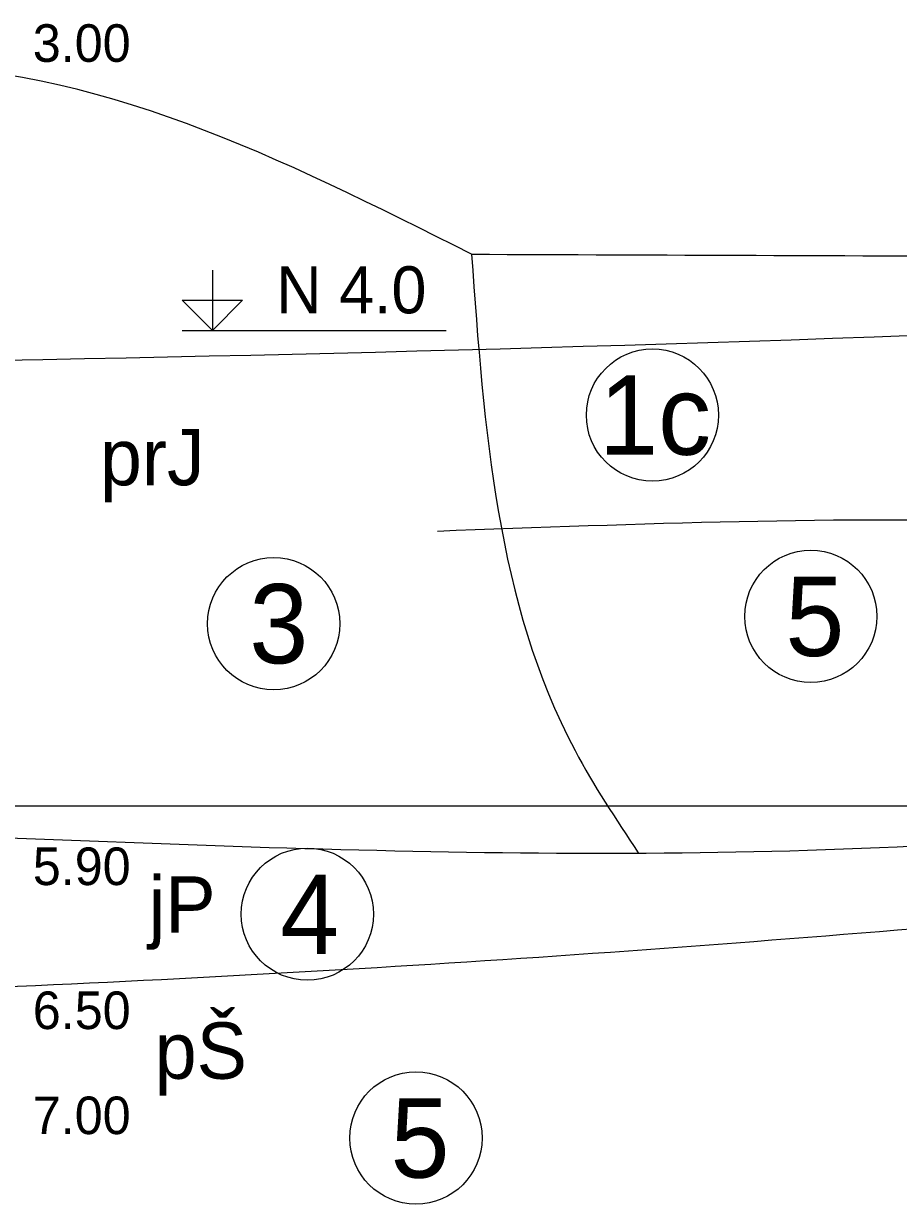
# Model space of a CAD drawing. Extents: x 3042 to 4120, y 576 to 2694.
# Drawn here: x 3433.83 to 3450.37, y 879.91 to 902.31 of the extents above; entities that cross this region are included whole.
import ezdxf

# ---------------------------------------------------------------- set-up
doc = ezdxf.new("R2010")
doc.units = 0
for name, color, linetype in [('52', 7, 'Continuous'), ('61', 7, 'Continuous'), ('HPV', 7, 'Continuous'), ('rozhraní', 7, 'Continuous')]:
    doc.layers.add(name, color=color, linetype=linetype)

msp = doc.modelspace()

# ---------------------------------------------------------------- linework, layer by layer
at = {"layer": '61'}
for points in [[(3437.3966062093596, 897.6520620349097), (3437.3966062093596, 896.5090620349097), (3436.8251062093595, 897.0805620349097), (3437.9681062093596, 897.0805620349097), (3437.3966062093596, 896.5090620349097)], [(3436.8251062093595, 896.5090620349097), (3441.8204562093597, 896.5090620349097)]]:
    msp.add_lwpolyline(points, dxfattribs=at)
at = {"layer": 'HPV'}
msp.add_spline([(3335.582962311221, 896.0481503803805), (3352.5717167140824, 896.0481503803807), (3453.0617167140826, 896.509755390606), (3557.3317167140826, 895.7898480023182), (3580.051716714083, 892.4898632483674), (3619.081666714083, 896.3928809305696), (3629.646992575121, 896.3928809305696)], degree=3, dxfattribs=at)
at = {"layer": 'rozhraní'}
for centre in [(3445.719485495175, 894.9085526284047), (3448.7150478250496, 891.1024646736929), (3438.5556742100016, 890.9639186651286), (3439.1920527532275, 885.4705530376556), (3441.2465060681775, 881.2381839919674)]:
    msp.add_circle(centre, 1.25, dxfattribs=at)
for points in [[(3442.2980689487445, 897.9504925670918), (3431.3317167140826, 901.5090620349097), (3430.030343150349, 901.4533469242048), (3426.6579803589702, 901.3354072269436), (3420.5505789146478, 901.1702916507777), (3409.5313912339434, 901.1164816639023), (3352.5717167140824, 896.4090620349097), (3327.8662573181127, 896.5362487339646)], [(3248.313660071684, 891.8591120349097), (3256.3217167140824, 891.8591120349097), (3352.5717167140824, 886.4090620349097), (3431.331691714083, 884.0090620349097), (3453.0617167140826, 885.4090620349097), (3491.5217167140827, 887.3591120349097), (3557.3317167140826, 884.6590620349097), (3580.051716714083, 895.0090120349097), (3619.0817167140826, 891.2590620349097), (3629.2745825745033, 891.2590620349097)], [(3442.2980689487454, 897.950492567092), (3453.0617167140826, 897.9090620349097), (3474.3006144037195, 897.8020620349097)], [(3442.2980689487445, 897.9504925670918), (3444.2548997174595, 888.5643431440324), (3445.451620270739, 886.6308541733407)], [(3441.6513317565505, 892.7166057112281), (3453.0631330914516, 892.8972495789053), (3455.728716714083, 892.801106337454)], [(3327.731251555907, 891.6486311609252), (3352.6357167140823, 891.4090620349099), (3372.3327436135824, 890.6912689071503), (3392.0153061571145, 889.3178217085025), (3411.682073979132, 887.8899946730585), (3431.3317167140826, 887.0090620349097), (3453.0617167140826, 886.9090620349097), (3491.5217167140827, 891.3591120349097), (3507.9473907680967, 889.8031245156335), (3524.476644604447, 888.6483564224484), (3540.9809344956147, 888.0489536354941), (3549.183548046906, 888.005684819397), (3553.26544223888, 888.0565884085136), (3557.3317167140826, 888.1590620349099), (3567.4684942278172, 889.0537677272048)], [(3518.8092174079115, 887.5130386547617), (3431.6794431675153, 887.5130386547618), (3407.745558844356, 887.5130386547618)], [(3311.776722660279, 872.8264542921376), (3352.5717167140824, 872.4090620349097), (3453.0617167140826, 876.9090620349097), (3491.5217167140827, 872.8591120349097), (3557.3317167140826, 880.1590620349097), (3580.051716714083, 879.0090120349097), (3619.0817167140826, 872.7591120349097), (3628.716834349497, 873.2727391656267)]]:
    msp.add_spline(points, degree=3, dxfattribs=at)

# ---------------------------------------------------------------- texts
at = {"layer": '52'}
for s, height, p in [('3.00', 0.7112000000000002, (3433.998716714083, 901.5880453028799)), ('prJ', 1.0668, (3435.268716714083, 893.5809120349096)), ('5.90', 0.7112000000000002, (3433.998716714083, 886.0207616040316)), ('jP', 1.0668, (3436.187765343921, 885.1182576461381)), ('6.50', 0.7112000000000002, (3433.998716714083, 883.2978448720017)), ('pŠ', 1.0668, (3436.3046729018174, 882.3579953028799)), ('7.00', 0.7112000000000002, (3433.998716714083, 881.3109620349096))]:
    msp.add_text(s, height=height, dxfattribs=at).set_placement(p)
at = {"layer": '61'}
msp.add_text('N 4.0', height=0.889, dxfattribs=at).set_placement((3438.6031062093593, 896.8329120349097))
at = {"layer": 'rozhraní'}
for s, p in [('1c', (3444.709501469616, 894.1585526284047)), ('5', (3448.2340174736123, 890.3524646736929)), ('3', (3438.0938131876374, 890.2139186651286)), ('4', (3438.676277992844, 884.7205530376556)), ('5', (3440.76547571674, 880.4881839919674))]:
    msp.add_text(s, height=1.5, dxfattribs=at).set_placement(p)

doc.saveas('drawing.dxf')
